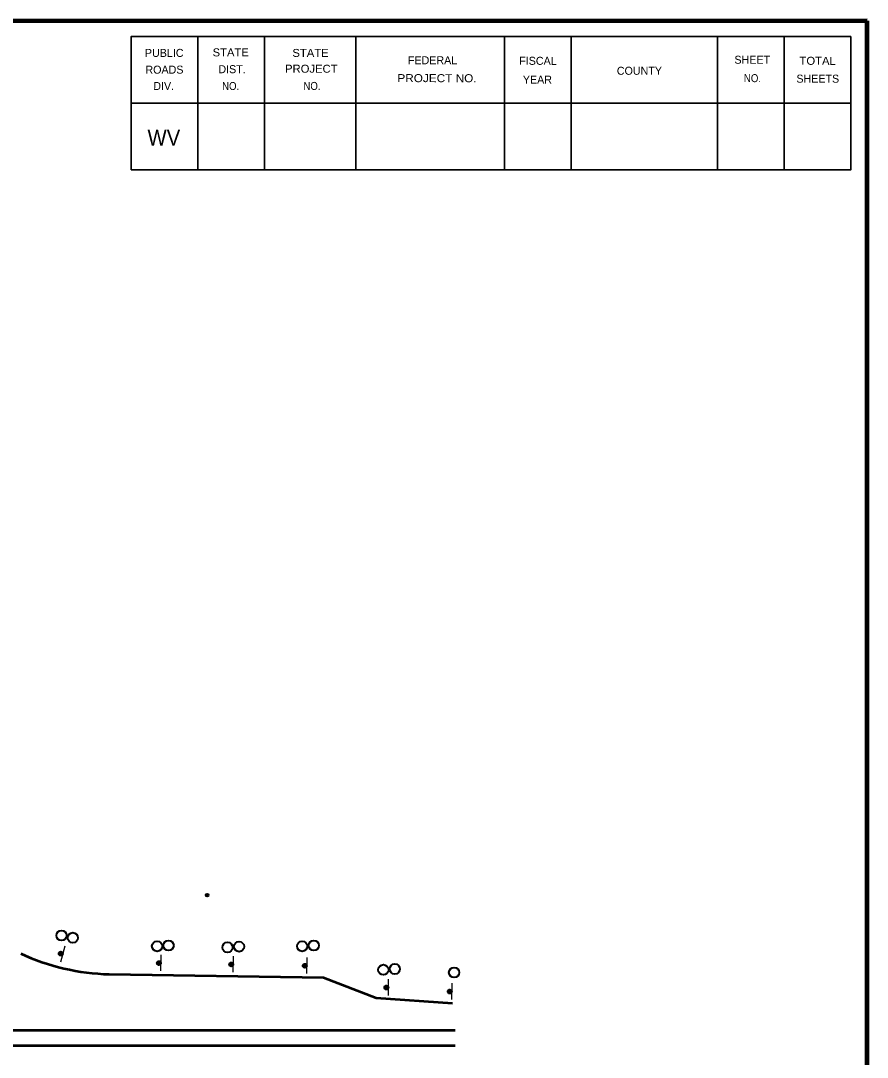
# Model space of a CAD drawing. Extents: x 393 to 1249, y -102 to 530.
# Drawn here: x 1080.9 to 1242.2, y 325.7 to 523.2 of the extents above; entities that cross this region are included whole.
import ezdxf

# ---------------------------------------------------------------- set-up
doc = ezdxf.new("R2010")
doc.units = 0
doc.header["$LTSCALE"] = 0.97
doc.header["$PDMODE"] = 32
doc.header["$PDSIZE"] = 0.485
for name, color, linetype, lineweight in [('1', 7, 'Continuous', 40), ('4', 7, 'Continuous', 25), ('61', 7, 'Continuous', 35)]:
    doc.layers.add(name, color=color, linetype=linetype, lineweight=lineweight)

msp = doc.modelspace()

# ---------------------------------------------------------------- linework, layer by layer
at = {"layer": '1', "lineweight": 158}
msp.add_line((1242.1684, -2.8845), (1242.1684, 523.2155), dxfattribs=at)
at = {"layer": '1', "lineweight": 13}
msp.add_line((1242.1684, -2.8845), (1242.1684, 523.2155), dxfattribs=at)
at = {"layer": '1', "lineweight": 53}
msp.add_line((955.6366, 327.898), (1163.6445, 327.898), dxfattribs=at)
at = {"layer": '1', "lineweight": 158}
msp.add_lwpolyline([(1242.1684, 523.2155), (450.4684, 523.1155), (450.5684, -2.8845)], dxfattribs=at)
at = {"layer": '1', "lineweight": 53}
for points in [[(1097.7912, 341.4779), (1138.6152, 340.8308), (1148.6275, 336.9899), (1163.172, 335.9728)], [(882.3469, 330.814), (955.6366, 330.814), (1163.6445, 330.814)]]:
    msp.add_lwpolyline(points, dxfattribs=at)
at = {"layer": '1'}
for centre, radius in [((1088.675, 348.8674), 0.972), ((1090.8314, 348.4362), 0.972), ((1106.8898, 346.8042), 0.972), ((1109.0843, 346.9457), 0.972), ((1122.5026, 346.7424), 0.972), ((1134.5396, 346.8042), 0.972), ((1136.7341, 346.9457), 0.972), ((1088.544, 345.4065), 0.3791), ((1088.5303, 345.4303), 0.3402), ((1088.5509, 345.3946), 0.35), ((1120.3081, 346.6008), 0.972), ((1088.5415, 345.3971), 0.3305), ((1088.544, 345.4065), 0.3013), ((1088.544, 345.4065), 0.2819), ((1088.5415, 345.3971), 0.2722), ((1088.5415, 345.3971), 0.2527), ((1088.5321, 345.3996), 0.2335), ((1088.5227, 345.4021), 0.2138), ((1088.4801, 345.3934), 0.1555), ((1088.4733, 345.4053), 0.1461), ((1088.5227, 345.4021), 0.1944), ((1088.504, 345.4071), 0.175), ((1088.4614, 345.3984), 0.1166), ((1088.452, 345.4009), 0.0977), ((1088.4426, 345.4034), 0.0778), ((1088.4238, 345.4085), 0.0583), ((1088.405, 345.4135), 0.0389), ((1088.3863, 345.4185), 0.0194), ((1088.5365, 345.3783), 0.1555), ((1088.539, 345.3877), 0.1069), ((1088.5417, 345.548), 0.00972), ((1107.2421, 343.5891), 0.3791), ((1107.223, 343.6089), 0.3402), ((1107.2516, 343.5792), 0.35), ((1107.2419, 343.5794), 0.3305), ((1107.2421, 343.5891), 0.3013), ((1107.2421, 343.5891), 0.2819), ((1107.2419, 343.5794), 0.2722), ((1107.2419, 343.5794), 0.2527), ((1107.2322, 343.5795), 0.2335), ((1107.2225, 343.5797), 0.2138), ((1107.2225, 343.5797), 0.1944), ((1107.1737, 343.5708), 0.1461), ((1107.1832, 343.561), 0.1555), ((1107.203, 343.5801), 0.175), ((1107.1638, 343.5613), 0.1166), ((1107.1541, 343.5615), 0.0977), ((1107.1444, 343.5616), 0.0778), ((1107.1249, 343.562), 0.0583), ((1107.1055, 343.5623), 0.0389), ((1107.0861, 343.5627), 0.0194), ((1107.2416, 343.5599), 0.1555), ((1107.2417, 343.5697), 0.1069), ((1107.2056, 343.7258), 0.00972), ((1121.0079, 343.3358), 0.3791), ((1120.9888, 343.3556), 0.3402), ((1121.0174, 343.3259), 0.35), ((1121.0077, 343.3261), 0.3305), ((1121.0079, 343.3358), 0.3013), ((1121.0079, 343.3358), 0.2819), ((1121.0077, 343.3261), 0.2722), ((1121.0077, 343.3261), 0.2527), ((1120.998, 343.3263), 0.2335), ((1120.9883, 343.3264), 0.2138), ((1120.9395, 343.3176), 0.1461), ((1120.949, 343.3077), 0.1555), ((1120.9688, 343.3268), 0.175), ((1120.9883, 343.3264), 0.1944), ((1120.9296, 343.308), 0.1166), ((1120.9199, 343.3082), 0.0977), ((1120.9102, 343.3083), 0.0778), ((1120.8907, 343.3087), 0.0583), ((1120.8713, 343.309), 0.0389), ((1120.8519, 343.3094), 0.0194), ((1121.0073, 343.3067), 0.1555), ((1121.0075, 343.3164), 0.1069), ((1120.9714, 343.4725), 0.00972), ((1135.027, 343.0824), 0.3791), ((1135.0079, 343.1022), 0.3402), ((1135.0366, 343.0726), 0.35), ((1135.0268, 343.0727), 0.3305), ((1135.027, 343.0824), 0.3013), ((1135.027, 343.0824), 0.2819), ((1135.0268, 343.0727), 0.2722), ((1135.0268, 343.0727), 0.2527), ((1135.0171, 343.0729), 0.2335), ((1135.0074, 343.0731), 0.2138), ((1134.9586, 343.0642), 0.1461), ((1134.9682, 343.0543), 0.1555), ((1135.0074, 343.0731), 0.1944), ((1134.988, 343.0734), 0.175), ((1134.9488, 343.0546), 0.1166), ((1134.939, 343.0548), 0.0977), ((1134.9293, 343.055), 0.0778), ((1134.8904, 343.0557), 0.0389), ((1134.9099, 343.0553), 0.0583), ((1134.871, 343.056), 0.0194), ((1135.0265, 343.0533), 0.1555), ((1135.0267, 343.063), 0.1069), ((1134.9905, 343.2192), 0.00972), ((1149.991, 342.3314), 0.972), ((1152.1855, 342.473), 0.972), ((1163.4629, 341.8063), 0.972), ((1150.5663, 338.9442), 0.3791), ((1150.5472, 338.964), 0.3402), ((1150.5758, 338.9343), 0.35), ((1150.5661, 338.9345), 0.3305), ((1150.5663, 338.9442), 0.3013), ((1150.5663, 338.9442), 0.2819), ((1150.5661, 338.9345), 0.2722), ((1150.5661, 338.9345), 0.2527), ((1150.5564, 338.9347), 0.2335), ((1150.5467, 338.9349), 0.2138), ((1150.4979, 338.926), 0.1461), ((1150.5075, 338.9161), 0.1555), ((1150.5467, 338.9349), 0.1944), ((1150.5273, 338.9352), 0.175), ((1150.488, 338.9164), 0.1166), ((1150.4783, 338.9166), 0.0977), ((1150.4686, 338.9168), 0.0778), ((1150.4297, 338.9174), 0.0389), ((1150.4492, 338.9171), 0.0583), ((1150.4103, 338.9178), 0.0194), ((1150.5658, 338.9151), 0.1555), ((1150.566, 338.9248), 0.1069), ((1150.5298, 339.081), 0.00972), ((1162.643, 338.1841), 0.3791), ((1162.6239, 338.2039), 0.3402), ((1162.6525, 338.1742), 0.35), ((1162.6428, 338.1744), 0.3305), ((1162.643, 338.1841), 0.3013), ((1162.643, 338.1841), 0.2819), ((1162.6428, 338.1744), 0.2722), ((1162.6428, 338.1744), 0.2527), ((1162.6331, 338.1746), 0.2335), ((1162.6234, 338.1747), 0.2138), ((1162.5746, 338.1659), 0.1461), ((1162.5842, 338.156), 0.1555), ((1162.6039, 338.1751), 0.175), ((1162.6234, 338.1747), 0.1944), ((1162.5647, 338.1563), 0.1166), ((1162.555, 338.1565), 0.0977), ((1162.5453, 338.1567), 0.0778), ((1162.5064, 338.1573), 0.0389), ((1162.5259, 338.157), 0.0583), ((1162.487, 338.1577), 0.0194), ((1162.6425, 338.155), 0.1555), ((1162.6427, 338.1647), 0.1069), ((1162.6065, 338.3209), 0.00972)]:
    msp.add_circle(centre, radius, dxfattribs=at)
at = {"layer": '1', "lineweight": 53}
msp.add_arc((1098.8496, 383.8411), 42.3765, 244.97058, 268.56877, dxfattribs=at)
at = {"layer": '1'}
msp.add_point((1116.4284, 356.5441), dxfattribs=at)
at = {"layer": '4'}
for p, q in [((1088.5535, 343.8644), (1089.3586, 346.8689)), ((1107.6243, 342.0952), (1107.6787, 345.2051)), ((1121.3901, 341.8419), (1121.4445, 344.9518)), ((1135.4093, 341.5885), (1135.4637, 344.6984)), ((1150.9486, 337.4503), (1151.0029, 340.5602)), ((1163.0252, 336.6902), (1163.0797, 339.8001))]:
    msp.add_line(p, q, dxfattribs=at)
for centre in [(1088.5465, 345.4158), (1107.2422, 343.5988), (1121.008, 343.3455), (1135.0272, 343.0922), (1150.5665, 338.9539), (1162.6432, 338.1938)]:
    msp.add_circle(centre, 0.3985, dxfattribs=at)
at = {"layer": '61'}
for p, q in [((1114.6684, 520.2155), (1114.6684, 494.8155)), ((1127.3684, 520.2155), (1127.3684, 494.8155)), ((1144.7684, 520.2155), (1144.7684, 494.8155)), ((1173.0684, 520.2155), (1173.0684, 494.8155)), ((1185.7684, 520.2155), (1185.7684, 494.8155)), ((1213.6684, 520.2155), (1213.6684, 494.8155)), ((1226.3684, 520.2155), (1226.3684, 494.8155)), ((1239.0684, 507.5155), (1101.9684, 507.5155))]:
    msp.add_line(p, q, dxfattribs=at)
for points in [[(1239.0684, 520.2155), (1101.9684, 520.2155), (1101.9684, 494.8155)], [(1239.0684, 520.2155), (1239.0684, 494.8155), (1101.9684, 494.8155)]]:
    msp.add_lwpolyline(points, dxfattribs=at)

# ---------------------------------------------------------------- texts
at = {"layer": '1', "width": 0.95}
msp.add_text('WV', height=3.048, dxfattribs=at).set_placement((1105.0684, 499.4155))
at = {"layer": '61'}
for s, height, rotation, p in [('PUBLIC', 1.525, 0.033, (1104.5684, 516.3155)), ('FEDERAL', 1.523, 0.007, (1154.6684, 514.9155)), ('FISCAL', 1.525, 359.942, (1175.8684, 514.8155)), ('SHEET', 1.525, 0.059, (1216.8684, 515.0155)), ('ROADS', 1.525, 0.124, (1104.6684, 513.1155)), ('DIST.', 1.525, 0.056, (1118.5684, 513.2155)), ('COUNTY', 1.523, 0.069, (1194.4684, 512.9155)), ('YEAR', 1.523, 0.105, (1176.5684, 511.2155)), ('SHEETS', 1.523, 359.959, (1228.6684, 511.4155)), ('DIV.', 1.525, 359.932, (1106.1684, 510.0155))]:
    msp.add_text(s, height=height, rotation=rotation, dxfattribs=at).set_placement(p)
for s, rotation, width, p in [('STATE', 0.059, 1.05, (1117.4684, 516.4155)), ('STATE', 0.059, 1.05, (1132.6684, 516.3155)), ('TOTAL', 359.926, 1.05, (1229.2684, 514.8155)), ('PROJECT', 359.908, 1.05, (1131.2684, 513.3155)), ('PROJECT NO.', 359.922, 1.1, (1152.6684, 511.5155)), ('NO.', 359.852, 0.9, (1218.6684, 511.5155)), ('NO.', 359.852, 0.9, (1119.2684, 510.0155)), ('NO.', 0.225, 0.9, (1134.7684, 510.0155))]:
    msp.add_text(s, height=1.525, rotation=rotation, dxfattribs=dict(at, width=width)).set_placement(p)

doc.saveas('drawing.dxf')
